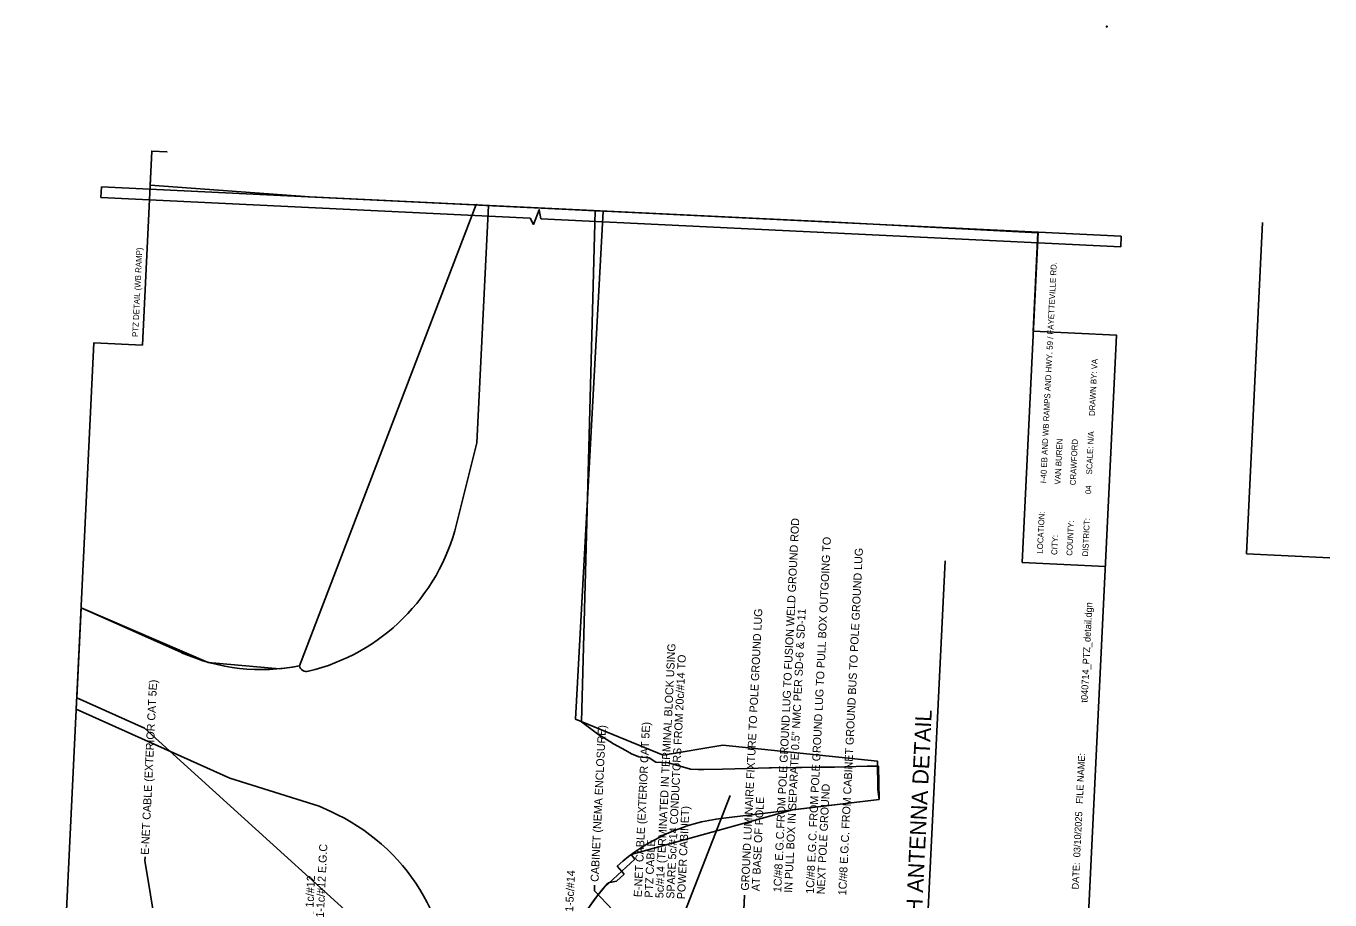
# Model space of a CAD drawing. Extents: x 590069 to 611209, y 383148 to 419683.
# Drawn here: x 610410 to 611209, y 419148 to 419683 of the extents above; entities that cross this region are included whole.
import ezdxf

# ---------------------------------------------------------------- set-up
doc = ezdxf.new("R2010")
doc.units = 0
for name, color, linetype in [('G-ANNO-TEXT', 7, 'Continuous'), ('G-No Plot-Stamp-1', 7, 'Continuous'), ('Level 10', 7, 'Continuous'), ('Level 57', 7, 'Continuous'), ('NO PLOT CELL', 7, 'Continuous'), ('T_Drafting', 7, 'Continuous')]:
    doc.layers.add(name, color=color, linetype=linetype)

msp = doc.modelspace()

# ---------------------------------------------------------------- linework, layer by layer
at = {"layer": 'G-No Plot-Stamp-1'}
for p, q in [((610456.54, 419584.84), (610456.23, 419578.32)), ((611081.21, 419554.71), (610456.54, 419584.84)), ((610456.23, 419578.32), (610719.19, 419565.63)), ((610686.57, 419428.11), (610693.57, 419573.41)), ((610693.57, 419573.41), (610758.91, 419570.26)), ((610725.66, 419565.32), (611080.89, 419548.19)), ((610758.91, 419570.26), (610750.6, 419257.14)), ((611080.89, 419548.19), (611081.21, 419554.71)), ((610674.1, 419378.26), (610686.57, 419428.11)), ((610441.11, 419264.94), (610444.11, 419327.13)), ((610444.11, 419327.13), (610505.7, 419299.59)), ((610932.53, 419230.17), (610932.91, 419209.75)), ((610589.92, 419205.49), (610535.31, 419222.8)), ((610596.98, 419202.34), (610589.92, 419205.49)), ((610932.91, 419209.75), (610837.54, 419198.32)), ((610776.72, 419164.03), (610772.1, 419159.72)), ((610772.39, 419168.87), (610776.72, 419164.03)), ((610766.53, 419158.17), (610762.82, 419153.91)), ((610767.03, 419158.7), (610766.53, 419158.17)), ((610772.1, 419159.72), (610767.03, 419158.7)), ((610758.43, 419148.27), (610755.6, 419144.22)), ((610762.82, 419153.91), (610758.43, 419148.27))]:
    msp.add_line(p, q, dxfattribs=at)
for points in [[(610669.41, 419084.31), (610482.98, 419253.33), (610441.45, 419271.91), (610444.11, 419327.13), (610522.05, 419293.66), (610565.66, 419289.76), (610573.62, 419290.79), (610577.85, 419291.57), (610686.04, 419574.03), (610686.19, 419574.06), (610687.65, 419573.7), (610763.89, 419570.02), (610746.93, 419258.77), (610800.57, 419236.91), (610837.25, 419242.97), (610931.93, 419233.07), (610932.19, 419215.71), (610932.91, 419209.75), (610879.8, 419203.38), (610781.04, 419175.91), (610783.18, 419173.13), (610764.64, 419156.01), (610760.43, 419150.85), (610754.75, 419142.88)], [(610719.19, 419565.63), (610721.14, 419561.82), (610724.76, 419570.78), (610725.66, 419565.32)], [(610535.31, 419222.8), (610441.11, 419264.94)], [(610750.6, 419257.14), (610761.2, 419249.3), (610763.99, 419247.65), (610770.25, 419243.77), (610777.67, 419239.73), (610781.21, 419237.7), (610785.74, 419235.78), (610792.13, 419235.14), (610796.17, 419232.53), (610803.64, 419232.19), (610803.89, 419232.16), (610817.26, 419228.19), (610821.96, 419228.1), (610821.96, 419228.1), (610825.57, 419228.03), (610836.96, 419228.32), (610851.97, 419228.67), (610865.5, 419228.97), (610866.97, 419228.98), (610881.96, 419229.17), (610885.5, 419229.21), (610896.96, 419229.4), (610905.5, 419229.55), (610911.96, 419229.71), (610925.5, 419230.06), (610926.96, 419230.08), (610932.53, 419230.17)]]:
    msp.add_lwpolyline(points, dxfattribs=at)
for centre, radius, start, end in [((610554.29, 419408.21), 123.5, 283.58478, 345.96376), ((610554.29, 419408.21), 119, 245.9, 281.418), ((610582.24, 419292.54), 4.5, 192.50139, 283.58478), ((610546.55, 419089.6), 123.5, 357.53575, 65.9), ((610851.71, 419080.16), 119, 96.83901, 131.80197)]:
    msp.add_arc(centre, radius, start, end, dxfattribs=at)
at = {"layer": 'Level 10'}
for p, q in [((611157.84, 419360.14), (611167.63, 419563.09)), ((611208.98, 419357.67), (611157.84, 419360.14))]:
    msp.add_line(p, q, dxfattribs=at)
at = {"layer": 'Level 57'}
for points in [[(611020.56, 419354.83), (611030.32, 419557.17)], [(611020.56, 419354.83), (611071.45, 419352.38)]]:
    msp.add_lwpolyline(points, dxfattribs=at)
at = {"layer": 'NO PLOT CELL'}
msp.add_lwpolyline([(610410.43, 418628.74), (611035.09, 418598.61), (611078.28, 419493.98), (611027.13, 419496.45), (611030.04, 419556.78), (610902.07, 419563.35), (610902.07, 419563.35), (610583.92, 419578.7), (610486.35, 419585.78), (610487.36, 419606.71), (610496.65, 419606.26), (610487.36, 419606.71), (610481.63, 419487.9), (610451.93, 419489.33)], close=True, dxfattribs=at)
msp.add_lwpolyline([(610410.43, 418628.74), (611035.09, 418598.61), (611078.28, 419493.98), (611027.13, 419496.45), (611030.04, 419556.78), (610902.07, 419563.35), (610902.07, 419563.35), (610583.92, 419578.7), (610486.35, 419585.78), (610487.36, 419606.71), (610496.65, 419606.26), (610487.36, 419606.71), (610481.63, 419487.9), (610451.93, 419489.33)], close=True, dxfattribs=at)
for radius in [0.302, 0.3, 0.3]:
    msp.add_circle((611072.3, 419683), radius, dxfattribs=at)
at = {"layer": 'T_Drafting'}
for p, q in [((610951.38, 418902.43), (610973.25, 419355.87)), ((610813.92, 419140.9), (610841.57, 419212.21)), ((610483.29, 419174.64), (610483.17, 419172.24)), ((610483.17, 419172.24), (610490.04, 419130.24)), ((610758.66, 419157.28), (610758.49, 419153.74)), ((610758.49, 419153.74), (610783.08, 419128.06)), ((610850.4, 419151.04), (610849.74, 419137.43))]:
    msp.add_line(p, q, dxfattribs=at)

# ---------------------------------------------------------------- texts
at = {"layer": 'G-ANNO-TEXT'}
msp.add_text('PTZ DETAIL (WB RAMP)', height=3.6, rotation=87.23861, dxfattribs=at).set_placement((610479.01, 419492.83))
at = {"layer": 'Level 10'}
for s, height, p in [('I-40 EB AND WB RAMPS AND HWY. 59 / FAYETTEVILLE RD.', 3.6, (611035.16, 419403.25)), ('DISTRICT:           04     SCALE: N/A       DRAWN BY: VA', 3.6, (611060.84, 419358.41)), ('VAN BUREN', 3.6, (611043.95, 419402.48)), ('CRAWFORD', 3.6, (611053.26, 419402.03)), ('LOCATION:   ', 3.6, (611033.08, 419360.1)), ('COUNTY:  ', 3.6, (611051.18, 419358.88)), ('CITY:       ', 3.6, (611041.87, 419359.33)), ('t040714_PTZ_detail.dgn', 4.2, (611060.56, 419268.95)), ('DATE:  03/10/2025   FILE NAME: ', 4.2, (611055.05, 419154.52))]:
    msp.add_text(s, height=height, rotation=87.23861, dxfattribs=at).set_placement(p)
at = {"layer": 'T_Drafting'}
for s, height, p in [('1C/#8 E.G.C.FROM POLE GROUND LUG TO FUSION WELD GROUND ROD', 4.9, (610872.95, 419152.81)), ('1C/#8 E.G.C. FROM POLE GROUND LUG TO PULL BOX OUTGOING TO ', 4.9, (610892.84, 419151.85)), ('1C/#8 E.G.C. FROM CABINET GROUND BUS TO POLE GROUND LUG', 4.9, (610912.73, 419150.89)), ('GROUND LUMINAIRE FIXTURE TO POLE GROUND LUG', 4.9, (610853.06, 419153.77)), ('IN PULL BOX IN SEPARATE 0.5" NMC PER SD-6 & SD-11', 4.9, (610879.58, 419152.49)), ('5c/#14 (TERMINATED IN TERMINAL BLOCK USING ', 4.9, (610800.71, 419149.14)), ('SPARE 5c/#14 CONDUCTORS FROM 20c/#14 TO ', 4.9, (610807.34, 419148.82)), ('E-NET CABLE (EXTERIOR CAT 5E)', 4.9, (610485.54, 419175.68)), ('PTZ CAMERA AND LOCAL RADIO WITH ANTENNA DETAIL', 9.8, (610947.82, 418904.43)), ('CABINET (NEMA ENCLOSURE)', 4.9, (610761.01, 419159.13)), ('E-NET CABLE (EXTERIOR CAT 5E)', 4.9, (610787.45, 419149.78)), ('NEXT POLE GROUND', 4.9, (610899.47, 419151.53)), ('AT BASE OF POLE', 4.9, (610859.69, 419153.45)), ('POWER CABINET)', 4.9, (610813.97, 419148.5)), ('1-1c/#12 E.G.C', 4.9, (610592.78, 419137.25)), ('PTZ CABLE', 4.9, (610794.08, 419149.46)), ('1-5c/#14', 4.9, (610745.45, 419140.74)), ('1-1c/#12', 4.9, (610586.15, 419137.57))]:
    msp.add_text(s, height=height, rotation=87.23861, dxfattribs=at).set_placement(p)

doc.saveas('drawing.dxf')
